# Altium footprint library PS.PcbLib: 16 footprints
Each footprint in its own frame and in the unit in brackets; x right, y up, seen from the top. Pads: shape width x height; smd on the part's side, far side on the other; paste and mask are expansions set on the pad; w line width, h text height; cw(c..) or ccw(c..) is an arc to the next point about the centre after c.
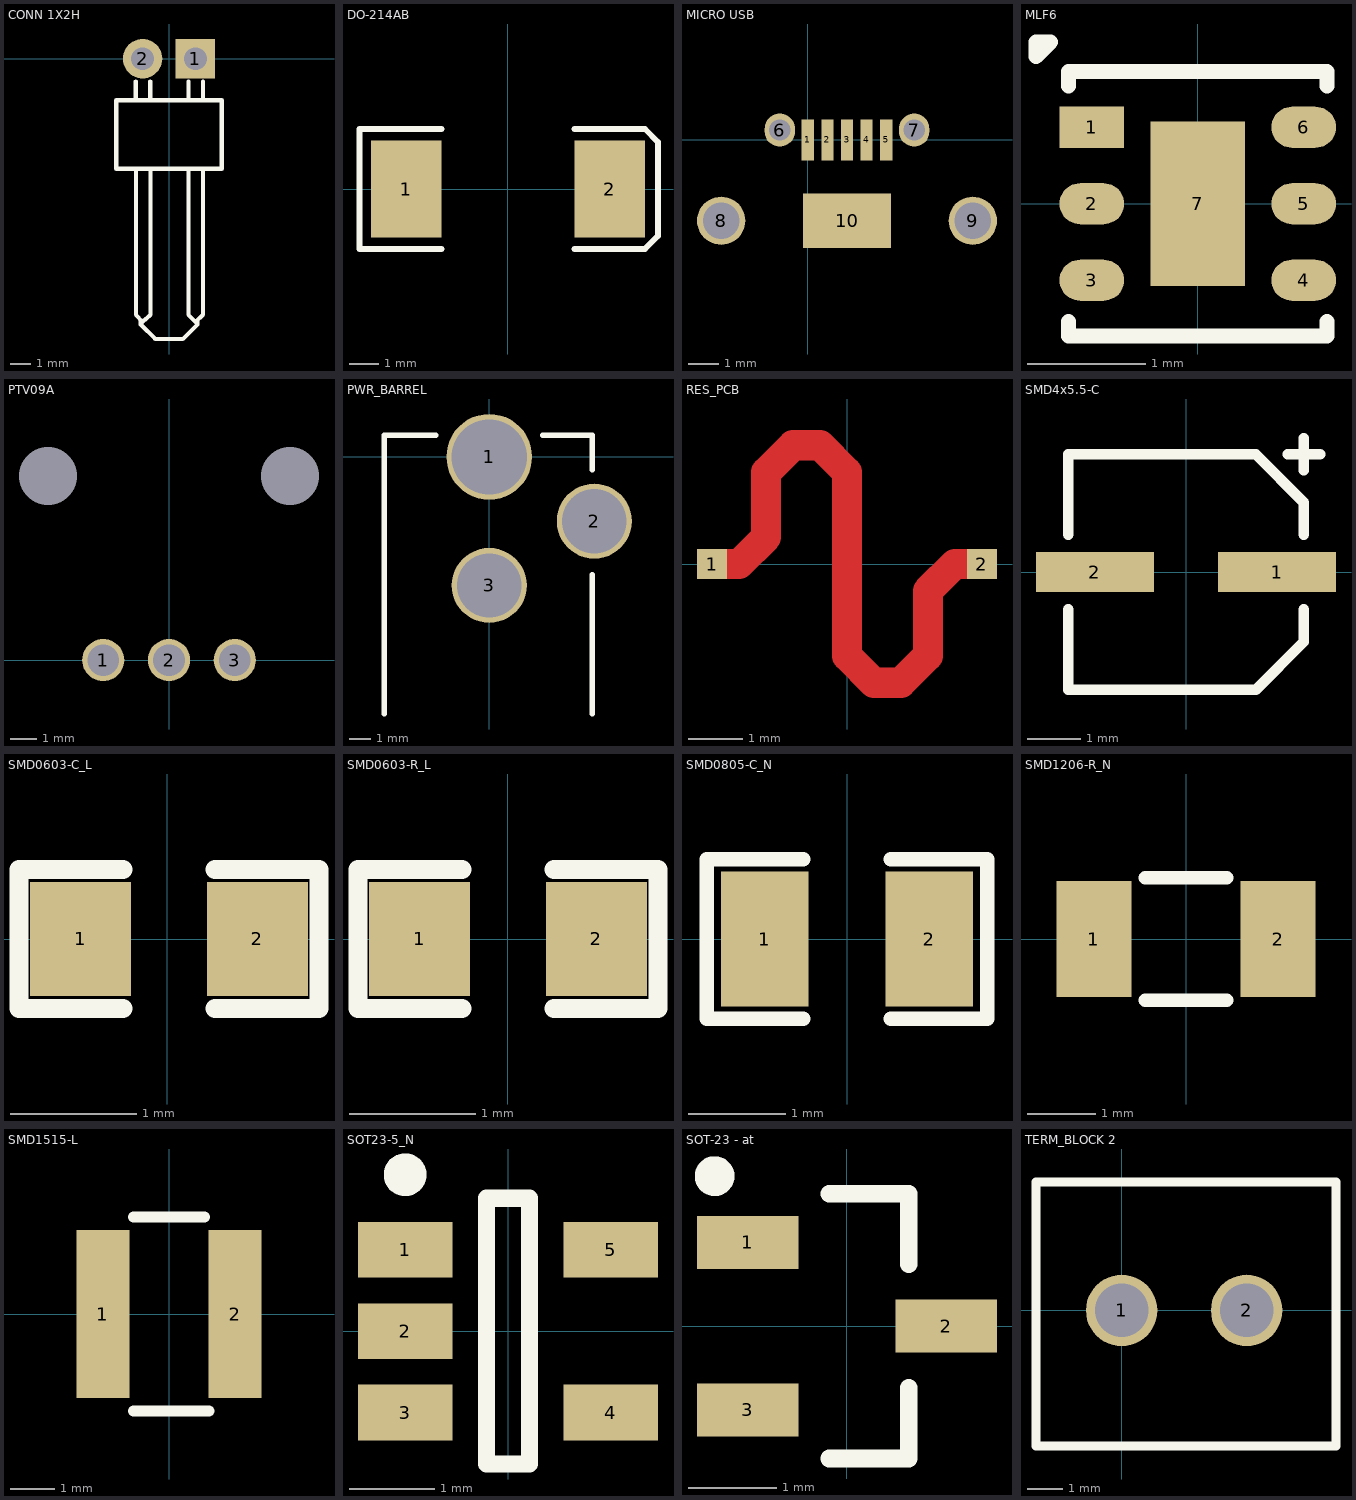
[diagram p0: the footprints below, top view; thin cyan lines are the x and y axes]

## CONN 1X2H [mm] "Connector; Header; 2 Position; Right Angle; 2.54mm/100mils"
pads (2):
  rect 1.9x1.9 hole 1.1: 1(1.27,0)
  round 1.9 hole 1.1: 2(-1.27,0)
Top Overlay:
  lines w0.2: -2.54,-5.3 -2.54,-2 2.54,-2 2.54,-5.3 -2.52,-5.3 ; -1.6,-2 -1.6,-1.1 ; -1.597,-5.3 -1.597,-12.335 -1.272,-12.675 -0.897,-12.335 -0.897,-5.3 ; -1.36,-12.6 -1.36,-12.8 -0.66,-13.5 0.665,-13.5 1.365,-12.8 1.365,-12.592 ; -0.9,-2 -0.9,-1.1 ; 0.94,-2 0.94,-1.1 ; 0.943,-5.3 0.943,-12.335 1.268,-12.675 1.643,-12.335 1.643,-5.3 ; 1.64,-2 1.64,-1.1
3D body: height 2.52, standoff -1.98, extent -2.5,-10.02 2.58,0.3

## DO-214AB [mm] "DO-214AB/SMC"
pads (2):
  rect 2.4x3.3 smd: 1(-3.475,0) 2(3.475,0)
Top Overlay:
  lines w0.2: -2.275,-2.05 -5.075,-2.05 -5.075,2.05 -2.275,2.05 ; 2.275,-2.05 4.675,-2.05 5.125,-1.6 5.125,1.6 4.68,2.05 2.275,2.05
3D body: height 2.4, standoff -0.05, extent -3.9,-2.95 3.9,2.95

## MICRO USB [mm] "type B, THT"
pads (10):
  rect 0.4x1.35 smd: 1(0,0) 2(0.65,0) 3(1.3,0) 4(1.95,0) 5(2.6,0)
  oval 1x1.1 hole 0.7: 6(-0.925,0.325) 7(3.525,0.325)
  round 1.6 hole 1.2: 8(-2.865,-2.675) 9(5.465,-2.675)
  rect 2.9x1.8 smd: 10(1.3,-2.675)
3D body: height 2.81, standoff -0.55, extent -3.025,-5.4 5.625,0.5

## MLF6 [mm] "2 x 2 mm"
pads (7):
  rect 0.55x0.35 smd: 1(-0.9,0.65)
  oval 0.55x0.35 smd: 2(-0.9,0) 3(-0.9,-0.65) 4(0.9,-0.65) 5(0.9,0) 6(0.9,0.65)
  rect 0.8x1.4 smd: 7(0,0)
Top Overlay:
  lines w0.127: -1.1,-1 -1.1,-1.125 1.1,-1.125 1.1,-1 ; -1.1,1 -1.1,1.125 1.1,1.125 1.1,1 ; -1.375,1.25 -1.25,1.375 -1.375,1.375 -1.375,1.25
3D body: height 0.85, standoff 0, extent -1,-1 1,1

## PTV09A [mm] "1-gang Panel-mounting Rotary Potentiometer"
pads (5):
  round 1.6 hole 1.2: 1(-2.5,0) 2(0,0) 3(2.5,0)
  round 0 hole 2.2 unplated: 4(-4.6,7) 5(4.6,7)
3D body: height 20.1, standoff -3.7, extent -4.876,-0.2 4.876,12.35

## PWR_BARREL [mm] "THT, 2.5 mm, DC socket"
pads (3):
  round 4 hole 3.5: 1(0,0)
  round 3.5 hole 3: 2(4.9,-3) 3(0,-6)
Top Overlay:
  lines w0.254: -4.9,-12 -4.9,1 -2.5,1 ; 2.5,1 4.8,1 4.8,-0.6 ; 4.8,-12 4.8,-5.5
3D body: height 11, standoff -3.5, extent -4.525,-13.75 5.175,0.75

## RES_PCB [mil] "Trace resistor, 10mOm at copper 35um"
pads (2):
  rect 22x22 smd: 1(-98.43,0) 2(98.43,0)
Top Layer:
  lines w22: -98.43,0 -78.74,0 -59.06,19.68 -59.06,66.93 -39.37,86.61 -19.69,86.61 0,66.93 0,-66.93 19.69,-86.61 39.37,-86.61 59.06,-66.93 59.06,-19.68 78.74,0 98.43,0

## SMD4x5.5-C [mm] "Electrolytic capacitor, SMD, radius 4mm, height 5.5mm"
pads (2):
  rect 2.2x0.75 smd: 1(1.7,0) 2(-1.7,0)
Top Overlay:
  lines w0.2: -2.2,-0.7 -2.2,-2.2 1.3,-2.2 2.2,-1.3 2.2,-0.7 ; -2.2,0.7 -2.2,2.2 1.3,2.2 2.2,1.3 2.2,0.7 ; 1.9,2.2 2.5,2.2 ; 2.2,1.9 2.2,2.5
3D body: height 5.4, standoff 0, extent -2.5,-2.15 2.5,2.15

## SMD0603-C_L [mm] "Ceramic capacitor 0603 (1608); high density"
pads (2):
  rect 0.8x0.9 smd: 1(-0.687,0) 2(0.713,0)
Top Overlay:
  lines w0.15: -0.349,-0.55 -1.174,-0.55 -1.174,0.55 -0.349,0.55 ; 0.376,-0.55 1.201,-0.55 1.201,0.55 0.376,0.55
3D body: height 0.77, standoff -0.03, extent -0.787,-0.4 0.813,0.4

## SMD0603-R_L [mm] "Resistor SMD 0603 (1608); high density"
pads (2):
  rect 0.8x0.9 smd: 1(-0.7,0) 2(0.7,0)
Top Overlay:
  lines w0.15: -0.362,-0.55 -1.187,-0.55 -1.187,0.55 -0.362,0.55 ; 0.363,-0.55 1.188,-0.55 1.188,0.55 0.363,0.55
3D body: height 0.45, standoff 0, extent -0.8,-0.4 0.8,0.4

## SMD0805-C_N [mm] "Ceramic capacitor 0805 (2012)"
pads (2):
  rect 0.9x1.4 smd: 1(-0.85,0) 2(0.85,0)
Top Overlay:
  lines w0.15: -1.45,0.8 -1.45,-0.825 -0.45,-0.825 ; -1.45,0.825 -0.45,0.825 ; 0.45,-0.825 1.45,-0.825 ; 0.45,0.825 1.45,0.825 ; 1.45,-0.8 1.45,0.8
3D body: height 0.63, standoff 0.03, extent -1,-0.625 1,0.625

## SMD1206-R_N [mm] "Resistor 1206 (3216)"
pads (2):
  rect 1.1x1.7 smd: 1(-1.35,0) 2(1.35,0)
Top Overlay:
  lines w0.2: -0.6,-0.9 0.6,-0.9 ; -0.6,0.9 0.6,0.9
3D body: height 0.6, standoff 0, extent -1.6,-0.8 1.6,0.8

## SMD1515-L [mm] "Power inductor 3.8x3.8mm; 3D model 3x3mm"
pads (2):
  rect 1.2x3.8 smd: 1(-1.5,0) 2(1.5,0)
Top Overlay:
  lines w0.254: -0.8,-2.2 0.9,-2.2 ; -0.8,2.2 0.8,2.2

## SOT23-5_N [mm] "SOT23, 5-Leads, Body 2.9x1.6mm, Pitch 0.95mm, Lead Span 2.7mm, IPC Medium Density"
height 1.45
pads (5):
  rect 1.1x0.65 smd: 1(-1.2,0.95) 2(-1.2,0) 3(-1.2,-0.95) 4(1.2,-0.95) 5(1.2,0.95)
Top Overlay:
  circle w0.25: c-1.2,1.825 r0.125
  lines w0.2: -0.25,-1.55 0.25,-1.55 0.25,1.55 -0.25,1.55 -0.25,-1.55
3D body: height 1.45, standoff 0, extent -1.4,-1.45 1.4,1.45

## SOT-23 - at [mm] "SOT23, 3-Leads, Altium power transistor, Body 2.9x1.3mm, Pitch 0.95mm,  IPC Medium Density"
height 1.1
pads (3):
  rect 1.15x0.6 smd: 1(-1.125,0.95) 2(1.125,0) 3(-1.125,-0.95)
Top Overlay:
  circle w0.25: c-1.5,1.7 r0.1
  lines w0.2: -0.2,-1.5 0.7,-1.5 0.7,-0.7 ; -0.2,1.5 0.7,1.5 0.7,0.7
3D body: height 1, standoff 0, extent -1.17,-1.46 1.17,1.46

## TERM_BLOCK 2 [mm] "3.5 mm"
pads (2):
  round 2 hole 1.5: 1(0,0) 2(3.5,0)
Top Overlay:
  lines w0.254: -2.4,-3.8 6,-3.8 6,3.6 -2.4,3.6 -2.4,-3.8
3D body: height 8.4, standoff -4.1, extent -2.225,-3.6 5.775,3.4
